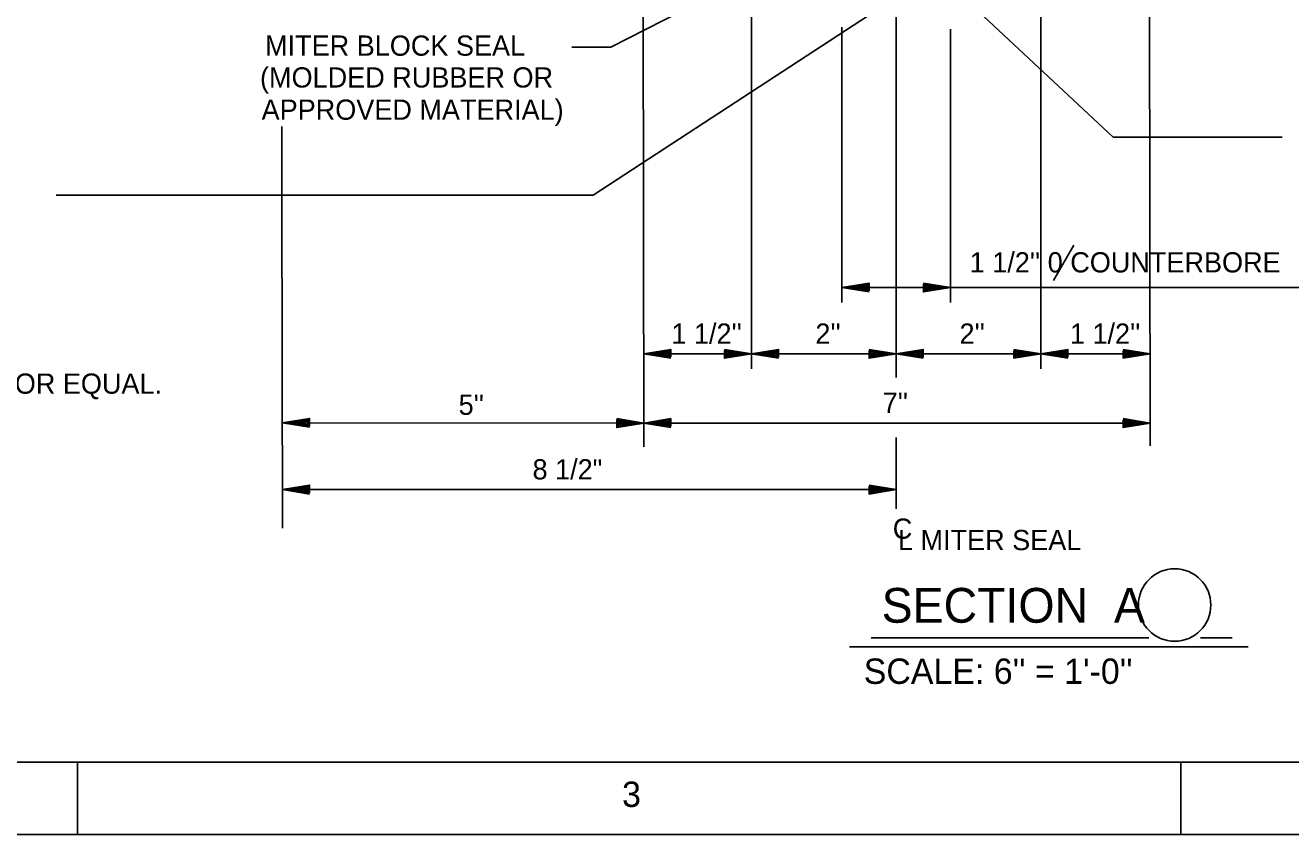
# Model space of a CAD drawing. Extents: x 0.04 to 6.71, y 0.04 to 4.71.
# Drawn here: x 2.753 to 4.21, y 0.042 to 0.973 of the extents above; entities that cross this region are included whole.
import ezdxf

# ---------------------------------------------------------------- set-up
doc = ezdxf.new("R2010")
doc.units = 0
for name, color, linetype in [('Level 1', 7, 'Continuous'), ('Level 25', 7, 'Continuous'), ('Level 3', 7, 'Continuous'), ('Level 50', 7, 'Continuous')]:
    doc.layers.add(name, color=color, linetype=linetype)

msp = doc.modelspace()

# ---------------------------------------------------------------- linework, layer by layer
at = {"layer": 'Level 1'}
for p, q in [((2.8125, 0.125), (2.8125, 0.0417)), ((4.0833, 0.125), (4.0833, 0.0417))]:
    msp.add_line(p, q, dxfattribs=at)
for points in [[(0.0417, 4.7083), (6.7083, 4.7083), (6.7083, 0.0417), (0.0417, 0.0417)], [(0.2917, 4.625), (6.625, 4.625), (6.625, 0.125), (0.2917, 0.125)]]:
    msp.add_lwpolyline(points, close=True, dxfattribs=at)
at = {"layer": 'Level 25'}
for p, q in [((3.5887, 1.7983), (3.5887, 0.5778)), ((3.9221, 1.6307), (3.9221, 0.5778)), ((3.7554, 0.5677), (3.7554, 1.4756)), ((3.4647, 0.4881), (3.4638, 1.0247)), ((4.048, 0.4891), (4.0471, 1.0258)), ((3.4066, 0.7775), (3.7422, 0.9965)), ((3.6929, 0.971), (3.6929, 0.6541)), ((3.8179, 0.9686), (3.8179, 0.6541)), ((3.0481, 0.7775), (3.048, 0.8567)), ((2.7882, 0.7775), (3.4066, 0.7775)), ((3.0488, 0.3946), (3.0481, 0.7775)), ((3.9364, 0.6794), (3.96, 0.7202)), ((3.6929, 0.6713), (3.6929, 0.6713)), ((3.6929, 0.6713), (3.8179, 0.6713)), ((3.8179, 0.6713), (4.2536, 0.6713)), ((3.8179, 0.6541), (3.8179, 0.6541)), ((3.4646, 0.595), (3.5887, 0.595)), ((3.5887, 0.595), (3.5887, 0.595)), ((3.5887, 0.595), (3.7554, 0.595)), ((3.6929, 0.595), (3.6929, 0.595)), ((3.7554, 0.595), (3.7554, 0.595)), ((3.7554, 0.595), (3.9221, 0.595)), ((3.8179, 0.595), (3.8179, 0.595)), ((3.8179, 0.595), (3.8179, 0.595)), ((3.9221, 0.595), (3.9221, 0.595)), ((3.9221, 0.595), (4.048, 0.595)), ((3.4646, 0.5154), (3.0486, 0.5157)), ((3.4646, 0.5154), (4.048, 0.5154)), ((3.7554, 0.4986), (3.7554, 0.4168)), ((3.0487, 0.4388), (3.7554, 0.4388))]:
    msp.add_line(p, q, dxfattribs=at)
at = {"layer": 'Level 3'}
for p, q in [((3.7266, 0.2681), (4.0464, 0.2681)), ((4.1421, 0.2681), (4.1056, 0.2681)), ((3.7016, 0.2577), (4.1606, 0.2577))]:
    msp.add_line(p, q, dxfattribs=at)
for points in [[(4.1997, 0.8444), (4.0051, 0.8444), (3.7704, 1.0637)], [(3.382, 0.9479), (3.4266, 0.9479), (3.5698, 1.0212)]]:
    msp.add_lwpolyline(points, dxfattribs=at)
msp.add_circle((4.076, 0.306), 0.0417, dxfattribs=at)
at = {"layer": 'Level 50'}
for p, q in [((3.6929, 0.6713), (3.6929, 0.6713)), ((3.7016, 0.6713), (3.7016, 0.6713)), ((3.8092, 0.6713), (3.8092, 0.6713)), ((3.8179, 0.6713), (3.8179, 0.6713)), ((3.4646, 0.595), (3.4646, 0.595)), ((3.4733, 0.595), (3.4733, 0.595)), ((3.5801, 0.595), (3.5801, 0.595)), ((3.5887, 0.595), (3.5887, 0.595)), ((3.5887, 0.595), (3.5887, 0.595)), ((3.5974, 0.595), (3.5974, 0.595)), ((3.7467, 0.595), (3.7467, 0.595)), ((3.7554, 0.595), (3.7554, 0.595)), ((3.7554, 0.595), (3.7554, 0.595)), ((3.7641, 0.595), (3.7641, 0.595)), ((3.9134, 0.595), (3.9134, 0.595)), ((3.9221, 0.595), (3.9221, 0.595)), ((3.9221, 0.595), (3.9221, 0.595)), ((3.9307, 0.595), (3.9307, 0.595)), ((4.0393, 0.595), (4.0393, 0.595)), ((4.048, 0.595), (4.048, 0.595)), ((3.0486, 0.5157), (3.0486, 0.5157)), ((3.0573, 0.5157), (3.0573, 0.5157)), ((3.456, 0.5154), (3.456, 0.5154)), ((3.4646, 0.5154), (3.4646, 0.5154)), ((3.4646, 0.5154), (3.4646, 0.5154)), ((3.4733, 0.5154), (3.4733, 0.5154)), ((4.0393, 0.5154), (4.0393, 0.5154)), ((4.048, 0.5154), (4.048, 0.5154)), ((3.0487, 0.4388), (3.0487, 0.4388)), ((3.0574, 0.4388), (3.0574, 0.4388)), ((3.7467, 0.4388), (3.7467, 0.4388)), ((3.7554, 0.4388), (3.7554, 0.4388))]:
    msp.add_line(p, q, dxfattribs=at)
for points in [[(3.7241, 0.6662), (3.6929, 0.6713), (3.7241, 0.6765), (3.7241, 0.6677), (3.7016, 0.6713), (3.7227, 0.6748), (3.7227, 0.6692), (3.7099, 0.6713), (3.7214, 0.6732), (3.7214, 0.6708), (3.7186, 0.6713)], [(3.7867, 0.6765), (3.8179, 0.6713), (3.7867, 0.6662), (3.7867, 0.675), (3.8092, 0.6713), (3.7881, 0.6678), (3.7881, 0.6735), (3.8009, 0.6713), (3.7894, 0.6695), (3.7894, 0.6718), (3.7922, 0.6713)], [(3.4958, 0.5899), (3.4646, 0.595), (3.4958, 0.6002), (3.4958, 0.5914), (3.4733, 0.595), (3.4945, 0.5985), (3.4945, 0.5929), (3.4816, 0.595), (3.4931, 0.5969), (3.4931, 0.5945), (3.4903, 0.595)], [(3.5576, 0.6002), (3.5887, 0.595), (3.5576, 0.5899), (3.5576, 0.5987), (3.5801, 0.595), (3.5589, 0.5915), (3.5589, 0.5972), (3.5717, 0.595), (3.5602, 0.5932), (3.5602, 0.5955), (3.5631, 0.595)], [(3.6199, 0.5899), (3.5887, 0.595), (3.6199, 0.6002), (3.6199, 0.5914), (3.5974, 0.595), (3.6186, 0.5985), (3.6186, 0.5929), (3.6057, 0.595), (3.6172, 0.5969), (3.6172, 0.5945), (3.6144, 0.595)], [(3.7242, 0.6002), (3.7554, 0.595), (3.7242, 0.5899), (3.7242, 0.5987), (3.7467, 0.595), (3.7256, 0.5915), (3.7256, 0.5972), (3.7384, 0.595), (3.7269, 0.5932), (3.7269, 0.5955), (3.7297, 0.595)], [(3.7866, 0.5899), (3.7554, 0.595), (3.7866, 0.6002), (3.7866, 0.5914), (3.7641, 0.595), (3.7852, 0.5985), (3.7852, 0.5929), (3.7724, 0.595), (3.7839, 0.5969), (3.7839, 0.5945), (3.7811, 0.595)], [(3.8909, 0.6002), (3.9221, 0.595), (3.8909, 0.5899), (3.8909, 0.5987), (3.9134, 0.595), (3.8922, 0.5915), (3.8922, 0.5972), (3.9051, 0.595), (3.8936, 0.5932), (3.8936, 0.5955), (3.8964, 0.595)], [(3.9532, 0.5899), (3.9221, 0.595), (3.9532, 0.6002), (3.9532, 0.5914), (3.9307, 0.595), (3.9519, 0.5985), (3.9519, 0.5929), (3.9391, 0.595), (3.9506, 0.5969), (3.9506, 0.5945), (3.9477, 0.595)], [(4.0168, 0.6002), (4.048, 0.595), (4.0168, 0.5899), (4.0168, 0.5987), (4.0393, 0.595), (4.0181, 0.5915), (4.0181, 0.5972), (4.031, 0.595), (4.0195, 0.5932), (4.0195, 0.5955), (4.0223, 0.595)], [(3.0798, 0.5105), (3.0486, 0.5157), (3.0798, 0.5208), (3.0798, 0.512), (3.0573, 0.5157), (3.0784, 0.5192), (3.0784, 0.5135), (3.0656, 0.5157), (3.0771, 0.5175), (3.0771, 0.5152), (3.0743, 0.5157)], [(3.4335, 0.5206), (3.4646, 0.5154), (3.4335, 0.5102), (3.4335, 0.5191), (3.456, 0.5154), (3.4348, 0.5119), (3.4348, 0.5176), (3.4476, 0.5154), (3.4361, 0.5136), (3.4361, 0.5159), (3.439, 0.5154)], [(3.4958, 0.5102), (3.4646, 0.5154), (3.4958, 0.5205), (3.4958, 0.5117), (3.4733, 0.5154), (3.4945, 0.5189), (3.4945, 0.5132), (3.4816, 0.5154), (3.4931, 0.5172), (3.4931, 0.5149), (3.4903, 0.5154)], [(4.0168, 0.5205), (4.048, 0.5154), (4.0168, 0.5102), (4.0168, 0.519), (4.0393, 0.5154), (4.0181, 0.5119), (4.0181, 0.5175), (4.031, 0.5154), (4.0195, 0.5135), (4.0195, 0.5159), (4.0223, 0.5154)], [(3.0799, 0.4336), (3.0487, 0.4388), (3.0799, 0.4439), (3.0799, 0.4351), (3.0574, 0.4388), (3.0786, 0.4423), (3.0786, 0.4366), (3.0657, 0.4388), (3.0772, 0.4406), (3.0772, 0.4383), (3.0744, 0.4388)], [(3.7242, 0.4439), (3.7554, 0.4388), (3.7242, 0.4336), (3.7242, 0.4424), (3.7467, 0.4388), (3.7256, 0.4353), (3.7256, 0.4409), (3.7384, 0.4388), (3.7269, 0.4369), (3.7269, 0.4393), (3.7297, 0.4388)]]:
    msp.add_lwpolyline(points, dxfattribs=at)

# ---------------------------------------------------------------- texts
at = {"layer": 'Level 1'}
msp.add_text('3', height=0.0292, dxfattribs=at).set_placement((3.4397, 0.0736))
at = {"layer": 'Level 25'}
for s, height, p in [('MITER BLOCK SEAL', 0.023292, (3.0286, 0.9381)), ('(MOLDED RUBBER OR', 0.023292, (3.0228, 0.9015)), ('APPROVED MATERIAL)', 0.023292, (3.0246, 0.8644)), ("1 1/2'' 0 COUNTERBORE", 0.023292, (3.84, 0.6887)), ("1 1/2''", 0.02329, (3.4965, 0.6067)), ("2''", 0.02329, (3.6623, 0.6067)), ("2''", 0.02329, (3.8283, 0.6067)), ("1 1/2''", 0.02329, (3.9554, 0.6067)), ('AS MFD. BY PECORA CORP. OR EQUAL.', 0.023292, (2.3077, 0.5491)), ("5''", 0.02329, (3.2515, 0.5248)), ("7''", 0.02329, (3.7398, 0.5271)), ('8 1/2"', 0.02329, (3.3366, 0.4505)), ('C', 0.0233, (3.7514, 0.3822)), ('L MITER SEAL', 0.023292, (3.7574, 0.3691)), ("SCALE: 6'' = 1'-0''", 0.029198, (3.718, 0.2152))]:
    msp.add_text(s, height=height, dxfattribs=at).set_placement(p)
at = {"layer": 'Level 3'}
msp.add_text('SECTION  A', height=0.04, dxfattribs=at).set_placement((3.7386, 0.2856))

doc.saveas('drawing.dxf')
